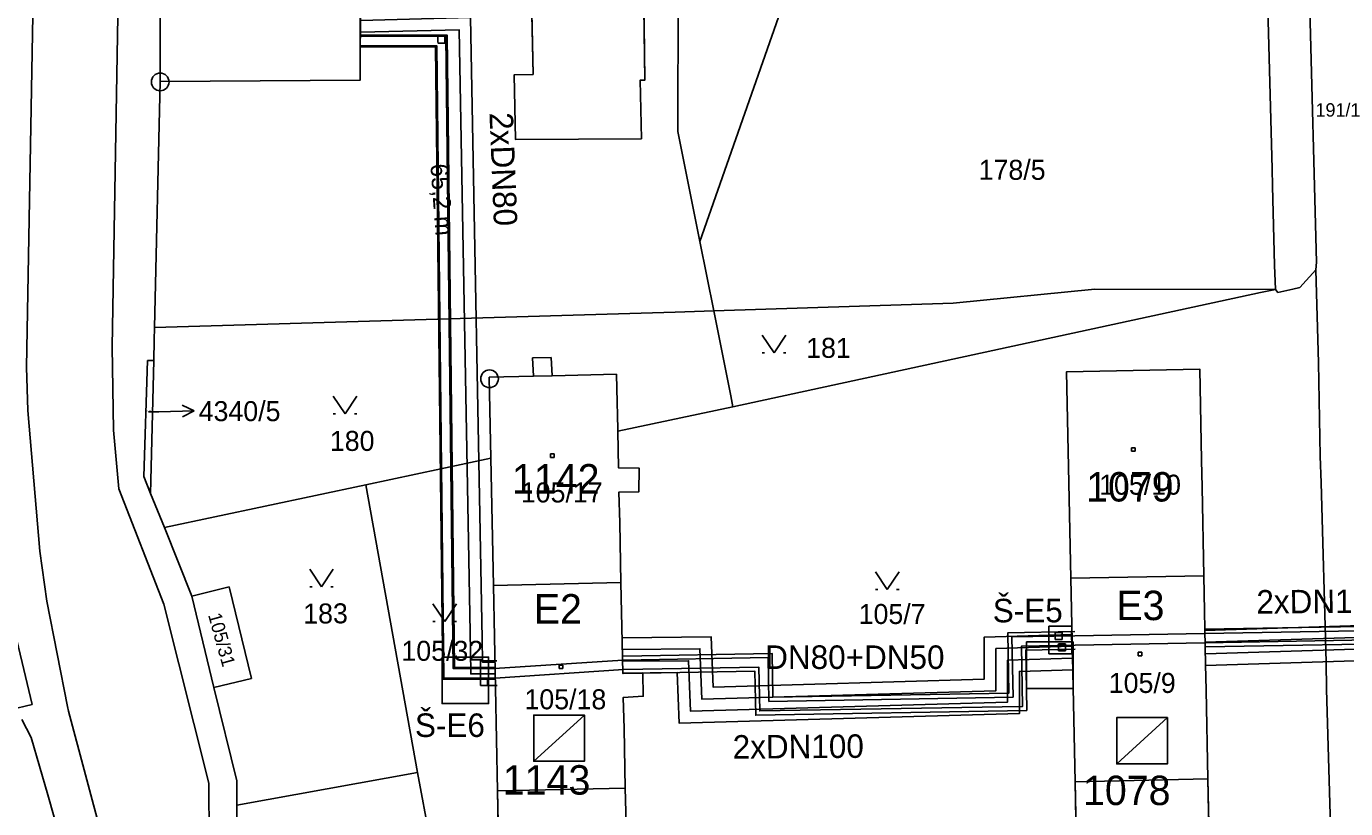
# Model space of a CAD drawing. Extents: x -468021 to -466942, y -1130484 to -1128584.
# Drawn here: x -467492.3 to -467380.2, y -1128809.3 to -1128742.8 of the extents above; entities that cross this region are included whole.
import ezdxf

# ---------------------------------------------------------------- set-up
doc = ezdxf.new("R2010")
doc.units = 0
for name, color, linetype in [('14a-Šachty', 7, 'Continuous'), ('16-PLÁN-DPST', 7, 'Continuous'), ('21-Označení-odběrného-místa', 7, 'Continuous'), ('22-Odběrná místa-šrafy', 7, 'Continuous'), ('25-Popisná-čísla', 7, 'Continuous'), ('27-delky-vedeni', 7, 'Continuous'), ('28-Topný kanál', 7, 'Continuous'), ('DKM', 7, 'Continuous'), ('TUV_SKUTEČNOST', 7, 'Continuous'), ('UT_PLÁN_předizolované potrubí', 7, 'Continuous'), ('UT_SKUTEČNOST_staré', 7, 'Continuous')]:
    doc.layers.add(name, color=color, linetype=linetype)

# ---------------------------------------------------------------- blocks, each defined once
blk = doc.blocks.new('SACHTA')
at = {"layer": '14a-Šachty'}
blk.add_lwpolyline([(-0.0000139, 0.0000235), (0.0000256, 0.0000235), (0.0000256, -0.000016), (-0.0000139, -0.000016)], close=True, dxfattribs=at)
blk = doc.blocks.new('VYM10')
at = {"layer": '16-PLÁN-DPST'}
blk.add_line((0.027, 0.0246), (-0.0237, -0.0216), dxfattribs=at)
for points in [[(0.027, 0.0246), (-0.0237, -0.0216), (0.027, -0.0216), (0.027, 0.0246)], [(0.027, 0.0246), (-0.0237, 0.0246), (-0.0237, -0.0216), (0.027, 0.0246)]]:
    blk.add_lwpolyline(points, dxfattribs=at)
blk.add_lwpolyline([(-0.0237, -0.0216), (0.027, -0.0216), (0.027, 0.0246), (-0.0237, 0.0246)], close=True, dxfattribs=at)

msp = doc.modelspace()

# ---------------------------------------------------------------- linework, layer by layer
at = {"layer": '22-Odběrná místa-šrafy'}
for points in [[(-467449.84, -1128718.82), (-467449.23, -1128746.89), (-467450.85, -1128746.93), (-467450.71, -1128752.43), (-467440.02, -1128752.36), (-467440.12, -1128747.38), (-467439.72, -1128747.37), (-467440.14, -1128718.74)], [(-467480.91, -1128723.22), (-467480.91, -1128747.5), (-467463.92, -1128747.38), (-467463.89, -1128731.02)], [(-467441.87, -1128785), (-467441.93, -1128782.39), (-467440.23, -1128782.36), (-467440.22, -1128780.35), (-467441.97, -1128780.32), (-467442.04, -1128777.22), (-467442.04, -1128777.04), (-467442.11, -1128773.58), (-467442.14, -1128772.38), (-467447.62, -1128772.5), (-467449.2, -1128772.54), (-467452.95, -1128772.63), (-467452.81, -1128779.52), (-467452.6, -1128790.34), (-467441.76, -1128790.07), (-467441.87, -1128785)], [(-467392.41, -1128779.68), (-467392.57, -1128771.94), (-467403.89, -1128772.16), (-467403.53, -1128789.7), (-467392.22, -1128789.5), (-467392.37, -1128781.96), (-467392.41, -1128779.68)], [(-467441.76, -1128790.07), (-467452.6, -1128790.34), (-467452.26, -1128807.79), (-467441.39, -1128807.56), (-467441.5, -1128802.47), (-467441.56, -1128799.84), (-467439.86, -1128799.74), (-467439.91, -1128797.76), (-467441.6, -1128797.81), (-467441.66, -1128795.15), (-467441.76, -1128790.07)], [(-467392.22, -1128789.5), (-467403.53, -1128789.7), (-467403.17, -1128807.01), (-467391.88, -1128806.75), (-467392.03, -1128799.23), (-467392.07, -1128797.03), (-467392.22, -1128789.5)], [(-467391.88, -1128806.75), (-467403.17, -1128807.01), (-467402.97, -1128816.79), (-467402.81, -1128824.58), (-467398.03, -1128824.48), (-467391.53, -1128824.35), (-467391.69, -1128816.52), (-467391.88, -1128806.75)], [(-467441.39, -1128807.56), (-467452.26, -1128807.79), (-467451.91, -1128825.5), (-467441.02, -1128825.27), (-467441.11, -1128821.14), (-467441.19, -1128817.25), (-467439.41, -1128817.3), (-467439.37, -1128815.14), (-467441.23, -1128815.2), (-467441.29, -1128812.62), (-467441.35, -1128809.56), (-467441.39, -1128807.56)]]:
    msp.add_lwpolyline(points, dxfattribs=at)
at = {"layer": '28-Topný kanál'}
for p, q in [((-467457.31, -1128743.64), (-467456.72, -1128743.64)), ((-467457.31, -1128743.69), (-467457.31, -1128744.19)), ((-467456.72, -1128744.24), (-467457.31, -1128744.24)), ((-467456.72, -1128743.64), (-467456.72, -1128744.24)), ((-467405.4, -1128793.79), (-467405.4, -1128796.14)), ((-467403.45, -1128793.79), (-467405.4, -1128793.79)), ((-467403.45, -1128796.14), (-467403.45, -1128793.79)), ((-467404.87, -1128794.31), (-467404.87, -1128794.91)), ((-467404.27, -1128794.31), (-467404.87, -1128794.31)), ((-467404.87, -1128794.91), (-467404.27, -1128794.91)), ((-467404.27, -1128794.91), (-467404.27, -1128794.31)), ((-467403.46, -1128794.19), (-467403.44, -1128795.75)), ((-467404.57, -1128795.28), (-467404.57, -1128795.88)), ((-467403.98, -1128795.28), (-467404.57, -1128795.28)), ((-467404.57, -1128795.88), (-467403.98, -1128795.88)), ((-467403.98, -1128795.88), (-467403.98, -1128795.28)), ((-467453.69, -1128796.74), (-467452.32, -1128796.74)), ((-467453.69, -1128798.84), (-467453.69, -1128796.74)), ((-467405.4, -1128796.14), (-467403.45, -1128796.14)), ((-467453.09, -1128798.24), (-467453.69, -1128798.24)), ((-467453.09, -1128798.84), (-467453.09, -1128798.24)), ((-467453.69, -1128798.84), (-467453.09, -1128798.84)), ((-467453.09, -1128798.84), (-467452.28, -1128798.84))]:
    msp.add_line(p, q, dxfattribs=at)
for points in [[(-467452.47, -1128797.29), (-467455.92, -1128797.29), (-467456.53, -1128743.56), (-467463.95, -1128743.56)], [(-467452.47, -1128798.29), (-467456.9, -1128798.29), (-467457.51, -1128744.55), (-467463.95, -1128744.55)], [(-467357.23, -1128801.99), (-467357.23, -1128804.13), (-467370.57, -1128804.45), (-467370.73, -1128793.67), (-467392.15, -1128794.05)], [(-467403.19, -1128794.25), (-467408.88, -1128794.35), (-467408.79, -1128799.47), (-467428.84, -1128799.83), (-467428.91, -1128796.1), (-467441.57, -1128796.33)], [(-467403.16, -1128795.74), (-467407.36, -1128795.82), (-467407.27, -1128800.94), (-467430.31, -1128801.35), (-467430.38, -1128797.62), (-467441.55, -1128797.82)], [(-467335.76, -1128801.33), (-467337.19, -1128801.36), (-467354.08, -1128805.55), (-467372.04, -1128805.98), (-467372.2, -1128795.2), (-467392.12, -1128795.54)]]:
    msp.add_lwpolyline(points, dxfattribs=at)
at = {"layer": 'DKM'}
for p, q in [((-467483.68, -1128690.53), (-467484.99, -1128770.04)), ((-467436.94, -1128751.74), (-467436.72, -1128693.78)), ((-467449.23, -1128746.89), (-467449.84, -1128718.82)), ((-467440.14, -1128718.74), (-467439.72, -1128747.37)), ((-467492.28, -1128771.77), (-467491.35, -1128719.96)), ((-467480.91, -1128723.22), (-467480.91, -1128747.5)), ((-467463.89, -1128731.02), (-467463.92, -1128747.38)), ((-467383.27, -1128738.89), (-467382.66, -1128762.84)), ((-467435.06, -1128761.1), (-467428.18, -1128741.45)), ((-467386.41, -1128754.91), (-467386.78, -1128741.28)), ((-467480.91, -1128747.5), (-467481.4, -1128768.41)), ((-467480.91, -1128747.5), (-467463.92, -1128747.38)), ((-467450.85, -1128746.93), (-467449.23, -1128746.89)), ((-467450.71, -1128752.43), (-467450.85, -1128746.93)), ((-467439.72, -1128747.37), (-467440.12, -1128747.38)), ((-467440.12, -1128747.38), (-467440.02, -1128752.36)), ((-467435.06, -1128761.1), (-467436.94, -1128751.74)), ((-467440.02, -1128752.36), (-467450.71, -1128752.43)), ((-467386.39, -1128756.39), (-467386.41, -1128754.91)), ((-467386.21, -1128763.11), (-467386.39, -1128756.39)), ((-467433.88, -1128766.99), (-467435.06, -1128761.1)), ((-467386.14, -1128765.18), (-467386.21, -1128763.11)), ((-467382.69, -1128763.49), (-467384.06, -1128765)), ((-467382.66, -1128762.84), (-467382.69, -1128763.49)), ((-467382.69, -1128763.49), (-467382.48, -1128771.39)), ((-467387.4, -1128765.44), (-467432.24, -1128775.14)), ((-467401.48, -1128765.13), (-467413.52, -1128766.32)), ((-467386.14, -1128765.18), (-467401.48, -1128765.13)), ((-467386.14, -1128765.18), (-467387.4, -1128765.44)), ((-467386.14, -1128765.18), (-467385.94, -1128765.43)), ((-467384.67, -1128765.14), (-467385.94, -1128765.43)), ((-467384.06, -1128765), (-467384.67, -1128765.14)), ((-467413.52, -1128766.32), (-467433.88, -1128766.99)), ((-467481.4, -1128768.41), (-467437.16, -1128767.1)), ((-467437.16, -1128767.1), (-467433.88, -1128766.99)), ((-467432.43, -1128774.2), (-467433.88, -1128766.99)), ((-467481.4, -1128768.41), (-467481.42, -1128769.47)), ((-467429.75, -1128769.05), (-467428.75, -1128770.55)), ((-467428.75, -1128770.55), (-467427.75, -1128769.05)), ((-467484.99, -1128770.04), (-467484.9, -1128777.13)), ((-467481.42, -1128769.47), (-467481.46, -1128771.21)), ((-467482, -1128771.2), (-467482.3, -1128781.06)), ((-467482, -1128771.2), (-467481.46, -1128771.21)), ((-467481.46, -1128771.21), (-467481.73, -1128782.5)), ((-467449.29, -1128770.97), (-467447.69, -1128770.94)), ((-467449.2, -1128772.54), (-467449.29, -1128770.97)), ((-467447.69, -1128770.94), (-467447.62, -1128772.5)), ((-467429.75, -1128770.55), (-467429.55, -1128770.55)), ((-467427.95, -1128770.55), (-467427.75, -1128770.55)), ((-467492.17, -1128775.46), (-467492.28, -1128771.77)), ((-467447.62, -1128772.5), (-467442.14, -1128772.38)), ((-467442.14, -1128772.38), (-467442.11, -1128773.58)), ((-467403.89, -1128772.16), (-467392.57, -1128771.94)), ((-467403.53, -1128789.7), (-467403.89, -1128772.16)), ((-467392.57, -1128771.94), (-467392.41, -1128779.68)), ((-467382.48, -1128771.39), (-467382.34, -1128779.34)), ((-467452.95, -1128772.63), (-467449.2, -1128772.54)), ((-467452.81, -1128779.52), (-467452.95, -1128772.63)), ((-467449.2, -1128772.54), (-467447.62, -1128772.5)), ((-467442.11, -1128773.58), (-467442.04, -1128777.04)), ((-467466.21, -1128774.23), (-467465.21, -1128775.73)), ((-467465.21, -1128775.73), (-467464.21, -1128774.23)), ((-467432.24, -1128775.14), (-467432.43, -1128774.2)), ((-467491.14, -1128787.42), (-467492.17, -1128775.46)), ((-467481.91, -1128775.58), (-467481.04, -1128775.56)), ((-467481.04, -1128775.56), (-467478.04, -1128775.47)), ((-467478.04, -1128775.47), (-467479.05, -1128775)), ((-467478.04, -1128775.47), (-467479.03, -1128776)), ((-467466.21, -1128775.73), (-467466.01, -1128775.73)), ((-467464.41, -1128775.73), (-467464.21, -1128775.73)), ((-467442.04, -1128777.22), (-467432.24, -1128775.14)), ((-467484.9, -1128777.13), (-467484.43, -1128782.1)), ((-467442.04, -1128777.04), (-467442.04, -1128777.22)), ((-467442.04, -1128777.22), (-467441.97, -1128780.32)), ((-467447.75, -1128779.15), (-467447.45, -1128779.15)), ((-467447.75, -1128779.45), (-467447.75, -1128779.15)), ((-467447.45, -1128779.15), (-467447.45, -1128779.45)), ((-467398.36, -1128778.62), (-467398.06, -1128778.62)), ((-467398.36, -1128778.92), (-467398.36, -1128778.62)), ((-467398.06, -1128778.92), (-467398.36, -1128778.92)), ((-467398.06, -1128778.62), (-467398.06, -1128778.92)), ((-467463.43, -1128781.77), (-467452.81, -1128779.52)), ((-467452.6, -1128790.34), (-467452.81, -1128779.52)), ((-467447.45, -1128779.45), (-467447.75, -1128779.45)), ((-467441.97, -1128780.32), (-467440.22, -1128780.35)), ((-467392.41, -1128779.68), (-467392.37, -1128781.96)), ((-467382.34, -1128779.34), (-467382.26, -1128781.59)), ((-467482.3, -1128781.06), (-467481.73, -1128782.5)), ((-467440.22, -1128780.35), (-467440.23, -1128782.36)), ((-467484.43, -1128782.1), (-467480.62, -1128791.92)), ((-467481.73, -1128782.5), (-467480.56, -1128785.41)), ((-467480.56, -1128785.41), (-467463.43, -1128781.77)), ((-467463.43, -1128781.77), (-467459.04, -1128806.22)), ((-467440.23, -1128782.36), (-467441.93, -1128782.39)), ((-467441.93, -1128782.39), (-467441.87, -1128785)), ((-467392.37, -1128781.96), (-467392.22, -1128789.5)), ((-467382.26, -1128781.59), (-467381.82, -1128796.85)), ((-467480.56, -1128785.41), (-467478.23, -1128791.24)), ((-467441.87, -1128785), (-467441.76, -1128790.07)), ((-467490.56, -1128791.66), (-467491.14, -1128787.42)), ((-467468.21, -1128788.95), (-467467.21, -1128790.45)), ((-467467.21, -1128790.45), (-467466.21, -1128788.95)), ((-467420.13, -1128789.17), (-467419.13, -1128790.67)), ((-467419.13, -1128790.67), (-467418.13, -1128789.17)), ((-467441.76, -1128790.07), (-467452.6, -1128790.34)), ((-467452.6, -1128790.34), (-467452.26, -1128807.79)), ((-467441.66, -1128795.15), (-467441.76, -1128790.07)), ((-467392.22, -1128789.5), (-467403.53, -1128789.7)), ((-467403.17, -1128807.01), (-467403.53, -1128789.7)), ((-467392.22, -1128789.5), (-467392.07, -1128797.03)), ((-467478.23, -1128791.24), (-467475.05, -1128790.44)), ((-467478.23, -1128791.24), (-467476.35, -1128798.99)), ((-467475.05, -1128790.44), (-467473.16, -1128798.22)), ((-467468.21, -1128790.45), (-467468.01, -1128790.45)), ((-467466.41, -1128790.45), (-467466.21, -1128790.45)), ((-467420.13, -1128790.67), (-467419.93, -1128790.67)), ((-467418.33, -1128790.67), (-467418.13, -1128790.67)), ((-467493.67, -1128792.59), (-467491.8, -1128800.45)), ((-467488.81, -1128800.62), (-467490.56, -1128791.66)), ((-467480.62, -1128791.92), (-467476.79, -1128807.14)), ((-467457.74, -1128791.9), (-467456.74, -1128793.4)), ((-467456.74, -1128793.4), (-467455.74, -1128791.9)), ((-467457.74, -1128793.4), (-467457.54, -1128793.4)), ((-467455.94, -1128793.4), (-467455.74, -1128793.4)), ((-467441.6, -1128797.81), (-467441.66, -1128795.15)), ((-467397.8, -1128796), (-467397.5, -1128796)), ((-467397.8, -1128796.3), (-467397.8, -1128796)), ((-467397.5, -1128796), (-467397.5, -1128796.3)), ((-467447, -1128797.09), (-467446.7, -1128797.09)), ((-467447, -1128797.39), (-467447, -1128797.09)), ((-467446.7, -1128797.09), (-467446.7, -1128797.39)), ((-467397.5, -1128796.3), (-467397.8, -1128796.3)), ((-467392.07, -1128797.03), (-467392.03, -1128799.23)), ((-467381.82, -1128796.85), (-467381.8, -1128799.14)), ((-467473.16, -1128798.22), (-467476.35, -1128798.99)), ((-467446.7, -1128797.39), (-467447, -1128797.39)), ((-467439.91, -1128797.76), (-467441.6, -1128797.81)), ((-467439.86, -1128799.74), (-467439.91, -1128797.76)), ((-467476.35, -1128798.99), (-467474.41, -1128806.92)), ((-467392.03, -1128799.23), (-467391.88, -1128806.75)), ((-467381.8, -1128799.14), (-467381.44, -1128811.74)), ((-467493.71, -1128800.9), (-467491.8, -1128800.45)), ((-467441.56, -1128799.84), (-467439.86, -1128799.74)), ((-467441.5, -1128802.47), (-467441.56, -1128799.84)), ((-467488.7, -1128801.01), (-467488.81, -1128800.62)), ((-467484.93, -1128815.22), (-467488.7, -1128801.01)), ((-467491.89, -1128803.26), (-467492.69, -1128801.72)), ((-467441.39, -1128807.56), (-467441.5, -1128802.47)), ((-467490.48, -1128808.13), (-467491.89, -1128803.26)), ((-467476.79, -1128807.14), (-467476.73, -1128817.19)), ((-467474.41, -1128806.92), (-467474.4, -1128808.99)), ((-467459.04, -1128806.22), (-467474.4, -1128808.99)), ((-467455.29, -1128826.25), (-467459.04, -1128806.22)), ((-467391.88, -1128806.75), (-467403.17, -1128807.01)), ((-467402.97, -1128816.79), (-467403.17, -1128807.01)), ((-467391.88, -1128806.75), (-467391.69, -1128816.52)), ((-467489.94, -1128810.01), (-467490.48, -1128808.13)), ((-467452.26, -1128807.79), (-467441.39, -1128807.56)), ((-467451.91, -1128825.5), (-467452.26, -1128807.79)), ((-467441.39, -1128807.56), (-467441.35, -1128809.56)), ((-467474.4, -1128808.99), (-467474.37, -1128817.82))]:
    msp.add_line(p, q, dxfattribs=at)
for centre, radius in [((-467480.92, -1128747.53), 0.75), ((-467480.92, -1128747.53), 0.01), ((-467452.93, -1128772.76), 0.75), ((-467452.93, -1128772.76), 0.01)]:
    msp.add_circle(centre, radius, dxfattribs=at)
at = {"layer": 'TUV_SKUTEČNOST'}
for points in [[(-467392.13, -1128794.14), (-467367.41, -1128793.37), (-467367.11, -1128805.1), (-467358.66, -1128804.88)], [(-467403.43, -1128794.49), (-467410.9, -1128794.73), (-467410.9, -1128798.3), (-467433.93, -1128798.96), (-467434.09, -1128794.7), (-467441.67, -1128794.77)], [(-467392.11, -1128795.14), (-467368.38, -1128794.4), (-467368.09, -1128806.13), (-467357.64, -1128805.85)], [(-467441.65, -1128795.77), (-467435.05, -1128795.71), (-467434.89, -1128799.98), (-467409.9, -1128799.27), (-467409.9, -1128795.69), (-467403.41, -1128795.49)]]:
    msp.add_lwpolyline(points, dxfattribs=at)
at = {"layer": 'UT_PLÁN_předizolované potrubí'}
for points in [[(-467452.47, -1128797.39), (-467456.01, -1128797.39), (-467456.63, -1128743.65), (-467463.95, -1128743.65)], [(-467452.47, -1128798.19), (-467456.8, -1128798.19), (-467457.41, -1128744.45), (-467463.95, -1128744.45)], [(-467403.18, -1128794.6), (-467408.53, -1128794.69), (-467408.43, -1128799.81), (-467429.19, -1128800.18), (-467429.25, -1128796.46), (-467441.57, -1128796.67)], [(-467392.14, -1128794.4), (-467403.18, -1128794.6)], [(-467335.79, -1128800.18), (-467337.34, -1128800.22), (-467354.24, -1128804.41), (-467370.91, -1128804.8), (-467371.07, -1128794.03), (-467392.14, -1128794.4)], [(-467335.77, -1128800.98), (-467337.24, -1128801.01), (-467354.13, -1128805.2), (-467371.7, -1128805.62), (-467371.86, -1128794.84), (-467392.13, -1128795.2)], [(-467403.17, -1128795.4), (-467407.71, -1128795.47), (-467407.62, -1128800.6), (-467429.97, -1128800.99), (-467430.03, -1128797.27), (-467441.55, -1128797.47)], [(-467392.13, -1128795.2), (-467403.17, -1128795.4)], [(-467452.5, -1128797.39), (-467441.59, -1128796.68)], [(-467452.45, -1128798.19), (-467441.54, -1128797.47)]]:
    msp.add_lwpolyline(points, dxfattribs=at)
at = {"layer": 'UT_SKUTEČNOST_staré'}
for points in [[(-467463.9, -1128742.31), (-467454.54, -1128742.06), (-467453.56, -1128794.87), (-467453.53, -1128796.84), (-467452.47, -1128796.84)], [(-467452.45, -1128797.84), (-467454.52, -1128797.84), (-467454.54, -1128795.87), (-467455.52, -1128743.09), (-467463.87, -1128743.31)], [(-467356.63, -1128806.82), (-467369.06, -1128807.15), (-467369.35, -1128795.43), (-467392.09, -1128796.14)], [(-467441.62, -1128796.77), (-467436.02, -1128796.72), (-467435.85, -1128801.01), (-467408.9, -1128800.24), (-467408.9, -1128796.66), (-467403.39, -1128796.49)], [(-467355.62, -1128807.79), (-467370.03, -1128808.18), (-467370.33, -1128796.46), (-467392.07, -1128797.14)], [(-467403.37, -1128797.49), (-467407.9, -1128797.63), (-467407.9, -1128801.21), (-467436.81, -1128802.04), (-467436.98, -1128797.73), (-467441.6, -1128797.77)]]:
    msp.add_lwpolyline(points, dxfattribs=at)

# ---------------------------------------------------------------- block references
at = {"layer": '14a-Šachty', "xscale": 100000, "yscale": 100000}
for p in [(-467405.89, -1128797.47), (-467455.57, -1128798.76)]:
    msp.add_blockref('SACHTA', p, dxfattribs=at)
at = {"layer": '16-PLÁN-DPST', "xscale": 84.9999999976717, "yscale": 85.00000000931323}
for p in [(-467447.16, -1128803.43), (-467397.61, -1128803.65)]:
    msp.add_blockref('VYM10', p, dxfattribs=at)

# ---------------------------------------------------------------- texts
at = {"layer": '14a-Šachty'}
for s, p in [('Š-E5', (-467410.16, -1128793.46)), ('Š-E6', (-467459.27, -1128803.2))]:
    msp.add_text(s, height=2, dxfattribs=at).set_placement(p)
at = {"layer": '21-Označení-odběrného-místa'}
for s, p in [('E2', (-467449.17, -1128793.56)), ('E3', (-467399.66, -1128793.27))]:
    msp.add_text(s, height=2.5, dxfattribs=at).set_placement(p)
at = {"layer": '25-Popisná-čísla'}
for s, p in [('1142', (-467451.02, -1128782.51)), ('1079', (-467402.23, -1128783.19)), ('1143', (-467451.8, -1128808.1)), ('1078', (-467402.49, -1128808.99))]:
    msp.add_text(s, height=2.5, dxfattribs=at).set_placement(p)
at = {"layer": '27-delky-vedeni'}
msp.add_text('65,2 m', height=1.5, rotation=274.2331, dxfattribs=at).set_placement((-467457.96, -1128754.53))
at = {"layer": 'DKM'}
for s, height, p in [('191/1', 1.14, (-467382.73, -1128750.48)), ('178/5', 1.7, (-467411.36, -1128755.85)), ('181', 1.7, (-467426.02, -1128770.98)), ('4340/5', 1.7, (-467477.65, -1128776.36)), ('4340/5', 0.1, (-467482.1, -1128775.54)), ('180', 1.7, (-467466.5, -1128778.89)), ('105/10', 1.7, (-467401.12, -1128782.61)), ('105/17', 1.7, (-467450.27, -1128783.27)), ('105/7', 1.7, (-467421.56, -1128793.6)), ('105/32', 1.7, (-467460.42, -1128796.73)), ('105/9', 1.7, (-467400.3, -1128799.46)), ('105/18', 1.7, (-467449.96, -1128800.85))]:
    msp.add_text(s, height=height, dxfattribs=at).set_placement(p)
for s, height, rotation, p in [('183', 1.7, 0.4463, (-467468.76, -1128793.57)), ('105/31', 1.14, 285.6021, (-467476.86, -1128792.83))]:
    msp.add_text(s, height=height, rotation=rotation, dxfattribs=at).set_placement(p)
at = {"layer": 'TUV_SKUTEČNOST'}
msp.add_text('DN80+DN50', height=2, dxfattribs=at).set_placement((-467429.5, -1128797.42))
at = {"layer": 'UT_SKUTEČNOST_staré'}
for s, rotation, p in [('2xDN80', 272.2986, (-467452.94, -1128750.16)), ('2xDN125', 0.3898, (-467387.75, -1128792.72)), ('2xDN100', 0.3898, (-467432.26, -1128805.05))]:
    msp.add_text(s, height=2, rotation=rotation, dxfattribs=at).set_placement(p)

doc.saveas('drawing.dxf')
